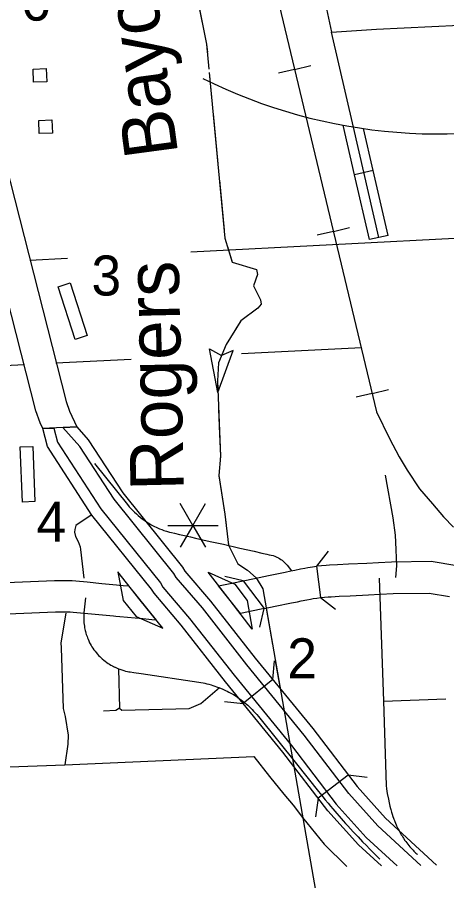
# Model space of a CAD drawing. Extents: x 1671357 to 13005564, y 567358 to 14261451.
# Drawn here: x 12758300.518 to 12758301.654, y 14259939.757 to 14259942.041 of the extents above; entities that cross this region are included whole.
import ezdxf

# ---------------------------------------------------------------- set-up
doc = ezdxf.new("R2010")
doc.units = 0
for name, color, linetype in [('10', 7, 'Continuous'), ('15', 7, 'Continuous'), ('31', 7, 'Continuous'), ('32', 7, 'Continuous'), ('33', 7, 'Continuous'), ('34', 7, 'Continuous'), ('37', 7, 'Continuous'), ('39', 7, 'Continuous'), ('40', 7, 'Continuous'), ('42', 7, 'Continuous'), ('43', 7, 'Continuous'), ('48', 7, 'Continuous'), ('5', 7, 'Continuous'), ('56', 7, 'Continuous'), ('6', 7, 'Continuous'), ('63', 7, 'Continuous')]:
    doc.layers.add(name, color=color, linetype=linetype)

msp = doc.modelspace()

# ---------------------------------------------------------------- linework, layer by layer
at = {"layer": '10'}
for p, q in [((12758301.6122, 14259940.6017), (12758301.5073, 14259940.6001)), ((12758301.6808, 14259940.5905), (12758301.6122, 14259940.6017)), ((12758301.5116, 14259940.5167), (12758301.6069, 14259940.518)), ((12758301.6069, 14259940.518), (12758301.6612, 14259940.5092))]:
    msp.add_line(p, q, dxfattribs=at)
for points in [[(12758301.5073, 14259940.6001), (12758301.4731, 14259940.5983), (12758301.4426, 14259940.5968), (12758301.3938, 14259940.5943), (12758301.3648, 14259940.5929), (12758301.3441, 14259940.5919), (12758301.3346, 14259940.5914), (12758301.3223, 14259940.5904), (12758301.3101, 14259940.589), (12758301.3097, 14259940.589), (12758301.3196, 14259940.5061)], [(12758301.1153, 14259940.5508), (12758301.1457, 14259940.5571), (12758301.1827, 14259940.5648), (12758301.2261, 14259940.5737), (12758301.2417, 14259940.577), (12758301.2521, 14259940.5791), (12758301.2673, 14259940.5823), (12758301.2787, 14259940.5843), (12758301.2868, 14259940.5858), (12758301.2991, 14259940.5877), (12758301.3097, 14259940.589)], [(12758300.4677, 14259940.5447), (12758300.5105, 14259940.547), (12758300.6164, 14259940.5512), (12758300.6309, 14259940.5516), (12758300.6426, 14259940.5516), (12758300.6492, 14259940.5516), (12758300.6554, 14259940.5514), (12758300.6635, 14259940.551), (12758300.6733, 14259940.5502), (12758300.7026, 14259940.5476), (12758300.7417, 14259940.5439), (12758300.7807, 14259940.54), (12758300.7871, 14259940.5394), (12758300.7976, 14259940.5383), (12758300.8123, 14259940.537), (12758300.8849, 14259940.4463)], [(12758301.0504, 14259940.5374), (12758301.0851, 14259940.5446), (12758301.1153, 14259940.5508), (12758301.1705, 14259940.477)], [(12758301.1705, 14259940.477), (12758301.1627, 14259940.4754), (12758301.1079, 14259940.464), (12758301.0504, 14259940.5374)], [(12758301.1705, 14259940.477), (12758301.1996, 14259940.4831), (12758301.2429, 14259940.492), (12758301.2586, 14259940.4952), (12758301.2691, 14259940.4974), (12758301.2833, 14259940.5003), (12758301.2937, 14259940.5022), (12758301.3006, 14259940.5035), (12758301.3104, 14259940.505), (12758301.3196, 14259940.5061)], [(12758301.3196, 14259940.5061), (12758301.3302, 14259940.5073), (12758301.3402, 14259940.5081), (12758301.3485, 14259940.5085), (12758301.3689, 14259940.5096), (12758301.3979, 14259940.511), (12758301.4468, 14259940.5134), (12758301.4774, 14259940.515), (12758301.5116, 14259940.5167)], [(12758300.8849, 14259940.4463), (12758300.8734, 14259940.4474), (12758300.8502, 14259940.4496), (12758300.7895, 14259940.4553), (12758300.7788, 14259940.4563), (12758300.7726, 14259940.457), (12758300.7337, 14259940.4608), (12758300.6949, 14259940.4645), (12758300.666, 14259940.467), (12758300.658, 14259940.4677), (12758300.6523, 14259940.468), (12758300.648, 14259940.4681), (12758300.6426, 14259940.4681), (12758300.632, 14259940.4681), (12758300.6191, 14259940.4678), (12758300.5144, 14259940.4636), (12758300.472, 14259940.4614)]]:
    msp.add_lwpolyline(points, dxfattribs=at)
at = {"layer": '15'}
for p, q in [((12758300.5858, 14259940.9531), (12758300.6147, 14259940.9546)), ((12758300.6389, 14259940.9559), (12758300.6752, 14259940.9578)), ((12758301.1934, 14259940.2894), (12758301.1158, 14259940.2261)), ((12758301.3932, 14259940.0365), (12758301.3136, 14259939.9757))]:
    msp.add_line(p, q, dxfattribs=at)
for points in [[(12758300.2887, 14259942.4326), (12758300.6474, 14259941.0247), (12758300.6563, 14259940.9997), (12758300.6752, 14259940.9578), (12758300.5858, 14259940.9531), (12758300.5788, 14259940.9686), (12758300.5675, 14259941.0004), (12758300.2052, 14259942.4222)], [(12758301.4811, 14259939.7963), (12758301.4207, 14259939.8521), (12758301.3394, 14259939.942), (12758301.2205, 14259940.0976), (12758301.069, 14259940.2835), (12758300.9518, 14259940.4332), (12758300.88, 14259940.5175), (12758300.8732, 14259940.5285), (12758300.7156, 14259940.7243), (12758300.5979, 14259940.9058), (12758300.5858, 14259940.9531)], [(12758300.6147, 14259940.9546), (12758300.6242, 14259940.9173), (12758300.7386, 14259940.7409), (12758300.8965, 14259940.5449), (12758300.9031, 14259940.5342), (12758300.9738, 14259940.4512), (12758301.0912, 14259940.3012), (12758301.2428, 14259940.1152), (12758301.3612, 14259939.9602), (12758301.4409, 14259939.872), (12758301.5222, 14259939.7969)], [(12758301.5852, 14259939.7978), (12758301.4718, 14259939.9026), (12758301.3946, 14259939.988), (12758301.2769, 14259940.1421), (12758301.1251, 14259940.3283), (12758301.0074, 14259940.4787), (12758300.9383, 14259940.5598), (12758300.9321, 14259940.57), (12758300.7738, 14259940.7664), (12758300.6832, 14259940.9061), (12758300.6389, 14259940.9559)], [(12758300.6752, 14259940.9578), (12758300.7058, 14259940.9234), (12758300.7968, 14259940.7831), (12758300.9553, 14259940.5863), (12758300.9613, 14259940.5765), (12758301.0294, 14259940.4966), (12758301.1473, 14259940.346), (12758301.2992, 14259940.1597), (12758301.4165, 14259940.0061), (12758301.492, 14259939.9226), (12758301.6263, 14259939.7985)]]:
    msp.add_lwpolyline(points, dxfattribs=at)
at = {"layer": '31'}
for points in [[(12758301.2743, 14259942.3704), (12758301.2746, 14259942.3478), (12758301.2777, 14259942.3215), (12758301.2816, 14259942.3005), (12758301.3037, 14259942.213), (12758301.3492, 14259942.0021)], [(12758301.3492, 14259942.0021), (12758301.4678, 14259942.0102), (12758302.0532, 14259942.0382)]]:
    msp.add_lwpolyline(points, dxfattribs=at)
at = {"layer": '32'}
for p, q in [((12758301.4589, 14259941.6361), (12758301.4101, 14259941.6249)), ((12758301.4984, 14259941.4643), (12758301.4496, 14259941.4531))]:
    msp.add_line(p, q, dxfattribs=at)
for points in [[(12758301.4068, 14259941.751), (12758301.3492, 14259942.0021)], [(12758301.4101, 14259941.6249), (12758301.3801, 14259941.7556)], [(12758301.474, 14259941.4587), (12758301.407, 14259941.7505)], [(12758301.4589, 14259941.6361), (12758301.4335, 14259941.7469)], [(12758301.4496, 14259941.4531), (12758301.4101, 14259941.6249)], [(12758301.4984, 14259941.4643), (12758301.4589, 14259941.6361)]]:
    msp.add_lwpolyline(points, dxfattribs=at)
at = {"layer": '33'}
for points in [[(12758300.7223, 14259940.861), (12758300.8093, 14259940.7524), (12758300.8142, 14259940.7463), (12758300.8189, 14259940.7412), (12758300.8236, 14259940.7363), (12758300.8277, 14259940.7323), (12758300.8329, 14259940.7275), (12758300.8375, 14259940.7234), (12758300.843, 14259940.7188), (12758300.8482, 14259940.7147), (12758300.8526, 14259940.7115), (12758300.8599, 14259940.7064), (12758300.8658, 14259940.7028), (12758300.8724, 14259940.6989), (12758300.8791, 14259940.6954), (12758300.8869, 14259940.6916), (12758300.894, 14259940.6885), (12758300.9, 14259940.6861), (12758300.9059, 14259940.6839), (12758300.9126, 14259940.6816), (12758300.9205, 14259940.6794), (12758300.926, 14259940.678), (12758300.9335, 14259940.6762), (12758300.9474, 14259940.6731), (12758300.96, 14259940.6702), (12758300.9763, 14259940.6667), (12758300.9896, 14259940.6636), (12758301.028, 14259940.655), (12758301.0633, 14259940.6471), (12758301.1068, 14259940.6372), (12758301.1444, 14259940.6287), (12758301.1651, 14259940.6241), (12758301.1782, 14259940.6211), (12758301.1844, 14259940.6197), (12758301.1892, 14259940.6187), (12758301.1943, 14259940.6172), (12758301.199, 14259940.6155), (12758301.2042, 14259940.6132), (12758301.2084, 14259940.6111), (12758301.2114, 14259940.6093), (12758301.2148, 14259940.6072), (12758301.2182, 14259940.6048), (12758301.2213, 14259940.6023), (12758301.2246, 14259940.5993), (12758301.2284, 14259940.5955), (12758301.2315, 14259940.5919), (12758301.2432, 14259940.5772)], [(12758301.4908, 14259940.8299), (12758301.511, 14259940.7174), (12758301.517, 14259940.6714), (12758301.5193, 14259940.6333), (12758301.5203, 14259940.6109), (12758301.5205, 14259940.5901), (12758301.5181, 14259940.5592)], [(12758301.4754, 14259940.5572), (12758301.4867, 14259940.2323), (12758301.4931, 14259940.0094)], [(12758300.6982, 14259940.5059), (12758300.6944, 14259940.4661), (12758300.6941, 14259940.4613), (12758300.6939, 14259940.4577), (12758300.6938, 14259940.4543), (12758300.6938, 14259940.4507), (12758300.6939, 14259940.4467), (12758300.694, 14259940.4436), (12758300.6944, 14259940.4391), (12758300.6948, 14259940.435), (12758300.6954, 14259940.4308), (12758300.6962, 14259940.4263), (12758300.6969, 14259940.4227), (12758300.6977, 14259940.4193), (12758300.6984, 14259940.4161), (12758300.6993, 14259940.4125), (12758300.7006, 14259940.4082), (12758300.7024, 14259940.4032), (12758300.7037, 14259940.3997), (12758300.7052, 14259940.396), (12758300.7073, 14259940.3914), (12758300.7094, 14259940.3869), (12758300.7112, 14259940.3836), (12758300.7133, 14259940.3798), (12758300.7155, 14259940.3762), (12758300.7181, 14259940.3722), (12758300.7209, 14259940.3682), (12758300.724, 14259940.3641), (12758300.7266, 14259940.3608), (12758300.7303, 14259940.3564), (12758300.7332, 14259940.3533), (12758300.7361, 14259940.3503), (12758300.7397, 14259940.3469), (12758300.7426, 14259940.3443), (12758300.7465, 14259940.3409), (12758300.7506, 14259940.3376), (12758300.7544, 14259940.3348), (12758300.7581, 14259940.3323), (12758300.7621, 14259940.3298), (12758300.7658, 14259940.3275), (12758300.7694, 14259940.3255), (12758300.7726, 14259940.3238), (12758300.7757, 14259940.3223), (12758300.7767, 14259940.3218), (12758300.7806, 14259940.3201), (12758300.7853, 14259940.3181), (12758300.7889, 14259940.3168), (12758300.7943, 14259940.3149), (12758300.7994, 14259940.3134), (12758300.8044, 14259940.312), (12758300.8092, 14259940.311), (12758300.8131, 14259940.3102), (12758300.8167, 14259940.3097), (12758300.8259, 14259940.3082), (12758300.8459, 14259940.3053), (12758300.9981, 14259940.2824), (12758301.0038, 14259940.2815), (12758301.0092, 14259940.2805), (12758301.0137, 14259940.2795), (12758301.0192, 14259940.2783), (12758301.025, 14259940.2768), (12758301.0307, 14259940.2752), (12758301.0351, 14259940.2738), (12758301.0402, 14259940.2723), (12758301.0452, 14259940.2705), (12758301.05, 14259940.2688), (12758301.0556, 14259940.2665), (12758301.0616, 14259940.2639), (12758301.0686, 14259940.2607), (12758301.0728, 14259940.2587), (12758301.0772, 14259940.2564), (12758301.0829, 14259940.2534), (12758301.0896, 14259940.2495), (12758301.0965, 14259940.2451), (12758301.101, 14259940.2421), (12758301.1052, 14259940.2393), (12758301.1098, 14259940.236), (12758301.1146, 14259940.2323), (12758301.12, 14259940.2279), (12758301.1239, 14259940.2247), (12758301.1273, 14259940.2216), (12758301.1318, 14259940.2174), (12758301.1358, 14259940.2137), (12758301.1391, 14259940.2104), (12758301.143, 14259940.2062), (12758301.1479, 14259940.2009), (12758301.1516, 14259940.1966), (12758301.1557, 14259940.1916), (12758301.2562, 14259940.0663), (12758301.3147, 14259939.9931), (12758301.3232, 14259939.9826), (12758301.3321, 14259939.9716), (12758301.3397, 14259939.9624), (12758301.3461, 14259939.9548), (12758301.3523, 14259939.9476), (12758301.358, 14259939.9409), (12758301.3629, 14259939.9351), (12758301.3692, 14259939.9281), (12758301.3748, 14259939.9216), (12758301.3798, 14259939.9159), (12758301.3863, 14259939.9089)], [(12758300.6464, 14259940.4651), (12758300.6335, 14259940.3864), (12758300.6344, 14259940.373), (12758300.6391, 14259940.2124), (12758300.6443, 14259940.1918), (12758300.6525, 14259940.1422), (12758300.652, 14259940.1187), (12758300.6441, 14259940.0638)], [(12758300.7856, 14259940.318), (12758300.788, 14259940.2135), (12758300.7946, 14259940.208), (12758300.9724, 14259940.2126), (12758301.0033, 14259940.2262), (12758301.0528, 14259940.268)], [(12758300.788, 14259940.2135), (12758300.7789, 14259940.2077), (12758300.7459, 14259940.2058)], [(12758301.4931, 14259940.0094), (12758301.4943, 14259940.0001), (12758301.4962, 14259939.9881), (12758301.4993, 14259939.9732), (12758301.5016, 14259939.9629), (12758301.5036, 14259939.9544), (12758301.5054, 14259939.9486), (12758301.5061, 14259939.9455), (12758301.507, 14259939.9418), (12758301.5079, 14259939.9386), (12758301.5093, 14259939.9337), (12758301.5113, 14259939.9273), (12758301.5128, 14259939.9229), (12758301.5138, 14259939.9201), (12758301.5152, 14259939.9164), (12758301.5162, 14259939.9137), (12758301.5181, 14259939.9091), (12758301.5197, 14259939.9054), (12758301.5211, 14259939.9023), (12758301.5225, 14259939.8993), (12758301.5239, 14259939.8964), (12758301.5253, 14259939.8935), (12758301.5277, 14259939.8889), (12758301.5307, 14259939.8835), (12758301.5336, 14259939.8786), (12758301.5354, 14259939.8756), (12758301.5373, 14259939.8726), (12758301.5394, 14259939.8694), (12758301.5433, 14259939.8637), (12758301.5454, 14259939.8609), (12758301.5479, 14259939.8574), (12758301.5506, 14259939.854), (12758301.5535, 14259939.8504), (12758301.5565, 14259939.8468), (12758301.5602, 14259939.8425), (12758301.5622, 14259939.8403), (12758301.5646, 14259939.8377), (12758301.5669, 14259939.8354), (12758301.5694, 14259939.8328), (12758301.5718, 14259939.8304), (12758301.5742, 14259939.8281), (12758301.5761, 14259939.8263)], [(12758301.3863, 14259939.9089), (12758301.3919, 14259939.9025), (12758301.3993, 14259939.8944), (12758301.406, 14259939.887), (12758301.4192, 14259939.873), (12758301.4313, 14259939.8602), (12758301.4411, 14259939.8502), (12758301.4492, 14259939.8418), (12758301.4571, 14259939.8339), (12758301.4648, 14259939.8263), (12758301.4736, 14259939.8176), (12758301.477, 14259939.8144)]]:
    msp.add_lwpolyline(points, dxfattribs=at)
at = {"layer": '34'}
for points in [[(12758300.7136, 14259940.7243), (12758300.6732, 14259940.6965), (12758300.6703, 14259940.686), (12758300.6695, 14259940.6793), (12758300.6723, 14259940.6676), (12758300.6788, 14259940.6545), (12758300.6821, 14259940.6476), (12758300.684, 14259940.6406), (12758300.6856, 14259940.6337), (12758300.6941, 14259940.558)], [(12758301.4867, 14259940.2323), (12758301.6511, 14259940.238)]]:
    msp.add_lwpolyline(points, dxfattribs=at)
at = {"layer": '37'}
for points in [[(12758301.3404, 14259940.6286), (12758301.3097, 14259940.589)], [(12758301.1153, 14259940.5508), (12758301.0665, 14259940.5622)], [(12758301.3196, 14259940.5061), (12758301.3592, 14259940.4754)], [(12758301.1591, 14259940.4283), (12758301.1705, 14259940.477)]]:
    msp.add_lwpolyline(points, dxfattribs=at)
at = {"layer": '39'}
for p, q in [((12758301.1546, 14259940.2577), (12758301.1546, 14259940.2577)), ((12758301.3534, 14259940.0061), (12758301.3534, 14259940.0061))]:
    msp.add_line(p, q, dxfattribs=at)
for points in [[(12758301.1934, 14259940.2894), (12758301.1985, 14259940.3392)], [(12758301.066, 14259940.2312), (12758301.1158, 14259940.2261)], [(12758301.4429, 14259940.0299), (12758301.3932, 14259940.0365)], [(12758301.3136, 14259939.9757), (12758301.307, 14259939.9261)]]:
    msp.add_lwpolyline(points, dxfattribs=at)
at = {"layer": '40'}
for p, q in [((12758301.2513, 14259941.9034), (12758301.2085, 14259941.8932)), ((12758301.2513, 14259941.9034), (12758301.2942, 14259941.9137)), ((12758301.354, 14259941.4749), (12758301.3112, 14259941.4646)), ((12758301.354, 14259941.4749), (12758301.3969, 14259941.4851)), ((12758301.4567, 14259941.0463), (12758301.4996, 14259941.0566)), ((12758301.4567, 14259941.0463), (12758301.4139, 14259941.036))]:
    msp.add_line(p, q, dxfattribs=at)
msp.add_lwpolyline([(12758301.0674, 14259942.6711), (12758301.4683, 14259940.9978), (12758301.5021, 14259940.9268), (12758301.5276, 14259940.8785), (12758301.549, 14259940.8432), (12758301.582, 14259940.7935), (12758301.6158, 14259940.7546), (12758301.6449, 14259940.7199), (12758301.6713, 14259940.6928)], dxfattribs=at)
at = {"layer": '42'}
for p, q in [((12758300.8434, 14259940.4997), (12758300.7839, 14259940.574)), ((12758300.7839, 14259940.574), (12758300.7984, 14259940.4983)), ((12758301.0811, 14259940.4981), (12758301.0227, 14259940.5733)), ((12758301.0227, 14259940.5733), (12758301.093, 14259940.5416)), ((12758301.093, 14259940.5416), (12758301.1262, 14259940.4988)), ((12758300.7984, 14259940.4983), (12758300.8321, 14259940.4561)), ((12758300.9029, 14259940.4254), (12758300.8434, 14259940.4997)), ((12758301.1395, 14259940.4229), (12758301.0811, 14259940.4981)), ((12758301.1262, 14259940.4988), (12758301.1395, 14259940.4229)), ((12758300.8321, 14259940.4561), (12758300.9029, 14259940.4254))]:
    msp.add_line(p, q, dxfattribs=at)
at = {"layer": '43'}
for p, q in [((12758301.026, 14259941.1639), (12758301.0584, 14259941.1465)), ((12758301.0483, 14259941.0488), (12758301.026, 14259941.1639)), ((12758301.0483, 14259941.0488), (12758301.0893, 14259941.1601)), ((12758301.0893, 14259941.1601), (12758301.0584, 14259941.1465))]:
    msp.add_line(p, q, dxfattribs=at)
for points in [[(12758300.9118, 14259943.1742), (12758301.0066, 14259942.7707), (12758300.8913, 14259942.67), (12758300.9679, 14259942.2228), (12758301.0188, 14259941.9701), (12758301.025, 14259941.9041)], [(12758300.9968, 14259942.0791), (12758301.0188, 14259941.9701), (12758301.0207, 14259941.9492)], [(12758301.0249, 14259941.9053), (12758301.025, 14259941.9041)], [(12758301.0258, 14259941.8952), (12758301.067, 14259941.4572), (12758301.0861, 14259941.3931), (12758301.1503, 14259941.3742), (12758301.1534, 14259941.3605), (12758301.1425, 14259941.3308), (12758301.161, 14259941.2939), (12758301.1633, 14259941.2821), (12758301.154, 14259941.272), (12758301.1091, 14259941.2387), (12758301.07, 14259941.1756), (12758301.0498, 14259941.1276), (12758301.0471, 14259941.0794), (12758301.055, 14259940.8801), (12758301.0507, 14259940.8289), (12758301.0666, 14259940.7267), (12758301.0767, 14259940.6452), (12758301.1015, 14259940.5955), (12758301.127, 14259940.5787), (12758301.1493, 14259940.5583), (12758301.167, 14259940.5294), (12758301.4068, 14259939.1559)], [(12758301.0258, 14259941.8952), (12758301.032, 14259941.8294)], [(12758301.0361, 14259941.7855), (12758301.0485, 14259941.6539)], [(12758301.0526, 14259941.61), (12758301.065, 14259941.4784)], [(12758301.0735, 14259941.4353), (12758301.0861, 14259941.3931), (12758301.1503, 14259941.3742), (12758301.1534, 14259941.3605), (12758301.1509, 14259941.3537)], [(12758301.1513, 14259941.3132), (12758301.161, 14259941.2939), (12758301.1633, 14259941.2821), (12758301.154, 14259941.272), (12758301.1091, 14259941.2387), (12758301.0938, 14259941.2141)], [(12758301.0706, 14259941.1766), (12758301.07, 14259941.1756), (12758301.0498, 14259941.1276), (12758301.0471, 14259941.0794), (12758301.0483, 14259941.0488)], [(12758301.0501, 14259941.0047), (12758301.0527, 14259940.9387)], [(12758301.0527, 14259940.9387), (12758301.055, 14259940.8801), (12758301.0544, 14259940.8727)], [(12758301.0508, 14259940.8287), (12758301.0666, 14259940.7267), (12758301.0702, 14259940.698)], [(12758301.0756, 14259940.6542), (12758301.0767, 14259940.6452), (12758301.1015, 14259940.5955), (12758301.1213, 14259940.5825)], [(12758301.176, 14259940.4782), (12758301.1927, 14259940.3824)], [(12758301.2003, 14259940.339), (12758301.2132, 14259940.2652)]]:
    msp.add_lwpolyline(points, dxfattribs=at)
at = {"layer": '48'}
for p, q in [((12758300.9825, 14259940.6971), (12758300.9491, 14259940.7549)), ((12758300.9825, 14259940.6971), (12758301.0159, 14259940.7549)), ((12758300.9158, 14259940.6971), (12758300.9825, 14259940.6971)), ((12758300.9825, 14259940.6971), (12758300.9491, 14259940.6393)), ((12758300.9825, 14259940.6971), (12758301.0493, 14259940.6971)), ((12758300.9825, 14259940.6971), (12758301.0159, 14259940.6393))]:
    msp.add_line(p, q, dxfattribs=at)
at = {"layer": '5'}
for points in [[(12758300.9768, 14259941.4209), (12758302.1008, 14259941.4787)], [(12758300.5516, 14259941.3991), (12758300.6508, 14259941.4042)]]:
    msp.add_lwpolyline(points, dxfattribs=at)
at = {"layer": '56'}
for points in [[(12758300.5611, 14259941.8695), (12758300.5598, 14259941.9042), (12758300.5946, 14259941.9056), (12758300.5959, 14259941.8709)], [(12758300.5762, 14259941.7337), (12758300.5749, 14259941.7684), (12758300.6097, 14259941.7698), (12758300.611, 14259941.7351)], [(12758300.6263, 14259941.3283), (12758300.6581, 14259941.3386), (12758300.7029, 14259941.1995), (12758300.6711, 14259941.1893)], [(12758300.5257, 14259940.905), (12758300.559, 14259940.9063), (12758300.5647, 14259940.7603), (12758300.5314, 14259940.759)]]:
    msp.add_lwpolyline(points, close=True, dxfattribs=at)
at = {"layer": '6'}
for points in [[(12758301.4279, 14259941.1668), (12758301.1106, 14259941.1509)], [(12758300.8191, 14259941.1362), (12758300.6197, 14259941.1262)], [(12758300.5369, 14259941.122), (12758300.0416, 14259941.0971)], [(12758300.3651, 14259940.4564), (12758300.3746, 14259940.054), (12758300.6441, 14259940.0638), (12758301.1439, 14259940.0859), (12758301.1853, 14259940.0326), (12758301.2225, 14259939.9861), (12758301.2473, 14259939.9573), (12758301.2719, 14259939.9247), (12758301.3297, 14259939.8543), (12758301.3895, 14259939.795)]]:
    msp.add_lwpolyline(points, dxfattribs=at)
at = {"layer": '63'}
msp.add_arc((12758301.6325, 14259943.1312), 1.3986, 243.494, 287.4375, dxfattribs=at)

# ---------------------------------------------------------------- texts
at = {"layer": '37'}
msp.add_text('2', height=0.1058, dxfattribs=at).set_placement((12758301.232, 14259940.2927))
at = {"layer": '43'}
for s, rotation, p in [('Bayou', 97.6642, (12758300.9437, 14259941.6801)), ('Rogers', 91.322, (12758300.9588, 14259940.7904))]:
    msp.add_text(s, height=0.14102, rotation=rotation, dxfattribs=at).set_placement(p)
at = {"layer": '56'}
for s, p in [('6', (12758300.5278, 14259942.0325)), ('3', (12758300.7141, 14259941.3053)), ('4', (12758300.569, 14259940.6539))]:
    msp.add_text(s, height=0.1058, dxfattribs=at).set_placement(p)

doc.saveas('drawing.dxf')
